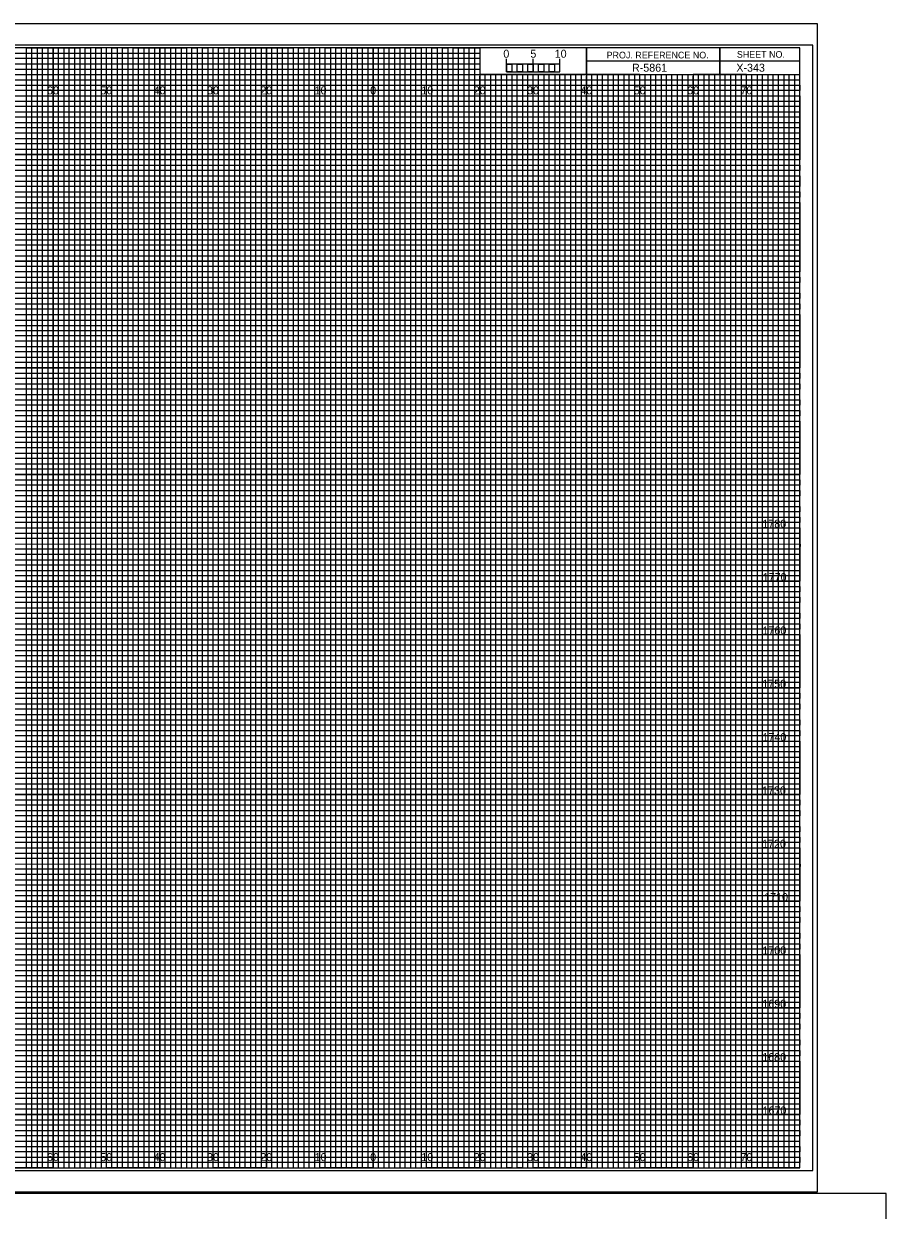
# Model space of a CAD drawing. Extents: x -13 to 1780, y -15 to 3284.
# Drawn here: x 901.7 to 1063.4, y 647.5 to 869.9 of the extents above; entities that cross this region are included whole.
import ezdxf

# ---------------------------------------------------------------- set-up
doc = ezdxf.new("R2010")
doc.units = 0
for name, color, linetype in [('Exist CMT Pavement', 7, 'Continuous'), ('Prop Retaining Wall', 7, 'Continuous'), ('Prop SS Cut Line', 7, 'Continuous'), ('Prop SS Fill Line', 7, 'Continuous'), ('Prop SS Transition Line', 7, 'Continuous'), ('Prop XS Bar Scale Labels', 7, 'Continuous'), ('Prop XS Earthwork Shape', 7, 'Continuous'), ('Prop XS Noise Wall', 7, 'Continuous'), ('Prop XS Retaining Wall', 7, 'Continuous'), ('Prop XS Station Labels', 7, 'Continuous'), ('Raster_Level_0', 7, 'Continuous'), ('Scratch_Level_3', 7, 'Continuous'), ('Scratch_Level_7', 7, 'Continuous'), ('Typical Bridge Rail CELL', 7, 'Continuous'), ('Typical Median Barrier CELL', 7, 'Continuous')]:
    doc.layers.add(name, color=color, linetype=linetype)

msp = doc.modelspace()

# ---------------------------------------------------------------- linework, layer by layer
at = {"layer": 'Prop Retaining Wall'}
for p, q in [((1032.16, 865.43), (1032.16, 860.43)), ((1032.16, 860.43), (1032.16, 865.43)), ((1007.16, 862.93), (1007.16, 860.43)), ((1047.16, 862.92), (1007.16, 862.92)), ((1007.16, 860.43), (1047.16, 860.43))]:
    msp.add_line(p, q, dxfattribs=at)
for points in [[(1047.16, 865.43), (727.16, 865.43), (727.16, 655.43), (1047.16, 655.43)], [(1007.16, 865.43), (987.16, 865.43), (987.16, 860.46), (1007.16, 860.46)], [(1047.16, 865.43), (1007.16, 865.43), (1007.16, 860.43), (1047.16, 860.43)]]:
    msp.add_lwpolyline(points, close=True, dxfattribs=at)
at = {"layer": 'Prop SS Cut Line'}
for points in [[(892.16, 655.43), (902.16, 655.43), (902.16, 865.43), (912.16, 865.43), (912.16, 655.43), (922.16, 655.43), (922.16, 865.43), (932.16, 865.43), (932.16, 655.43), (942.16, 655.43), (942.16, 865.43), (952.16, 865.43), (952.16, 655.43), (962.16, 655.43), (962.16, 865.43), (972.16, 865.43), (972.16, 655.43), (982.16, 655.43), (982.16, 865.43), (987.09, 865.43), (987.16, 865.43), (987.16, 860.43), (992.15, 860.43), (992.15, 655.43), (1002.16, 655.43), (1002.16, 860.43), (1012.16, 860.43), (1012.16, 655.43), (1022.16, 655.43), (1022.16, 860.43), (1032.16, 860.43), (1032.16, 655.43), (1042.16, 655.43), (1042.16, 860.43)], [(727.16, 860.43), (1002.16, 860.43)], [(727.16, 840.43), (1047.16, 840.43), (1047.16, 850.43), (727.16, 850.43)], [(727.16, 820.43), (1047.16, 820.43), (1047.16, 830.43), (727.16, 830.43)], [(727.16, 800.43), (1047.16, 800.43), (1047.16, 810.43), (727.16, 810.43)], [(727.16, 780.43), (1047.16, 780.43), (1047.16, 790.43), (727.16, 790.43)], [(727.16, 760.43), (1047.16, 760.43), (1047.16, 770.43), (727.16, 770.43)], [(727.16, 740.43), (1047.16, 740.43), (1047.16, 750.43), (727.16, 750.43)], [(727.16, 720.43), (1047.16, 720.43), (1047.16, 730.43), (727.16, 730.43)], [(727.16, 700.43), (1047.16, 700.43), (1047.16, 710.43), (727.16, 710.43)], [(727.16, 680.43), (1047.16, 680.43), (1047.16, 690.43), (727.16, 690.43)], [(727.16, 660.43), (1047.16, 660.43), (1047.16, 670.43), (727.16, 670.43)]]:
    msp.add_lwpolyline(points, dxfattribs=at)
at = {"layer": 'Prop SS Fill Line'}
for p, q in [((917.16, 865.43), (907.16, 865.43)), ((907.16, 865.43), (907.16, 655.43)), ((917.16, 655.43), (917.16, 865.43)), ((937.16, 865.43), (927.16, 865.43)), ((927.16, 865.43), (927.16, 655.43)), ((937.16, 655.43), (937.16, 865.43)), ((957.16, 865.43), (947.16, 865.43)), ((947.16, 865.43), (947.16, 655.43)), ((957.16, 655.43), (957.16, 865.43)), ((977.16, 865.43), (967.16, 865.43)), ((967.16, 865.43), (967.16, 655.43)), ((977.16, 655.43), (977.16, 865.43)), ((987.16, 865.43), (987.16, 655.43)), ((997.16, 655.43), (997.16, 860.43)), ((1017.16, 860.43), (1007.16, 860.43)), ((1007.16, 860.43), (1007.16, 655.43)), ((1017.16, 655.43), (1017.16, 860.43)), ((1037.16, 860.43), (1027.16, 860.43)), ((1027.16, 860.43), (1027.16, 655.43)), ((1037.16, 655.43), (1037.16, 860.43)), ((907.16, 655.43), (897.16, 655.43)), ((927.16, 655.43), (917.16, 655.43)), ((947.16, 655.43), (937.16, 655.43)), ((967.16, 655.43), (957.16, 655.43)), ((987.16, 655.43), (977.16, 655.43)), ((1007.16, 655.43), (997.16, 655.43)), ((1027.16, 655.43), (1017.16, 655.43)), ((1047.16, 655.43), (1037.16, 655.43)), ((1047.16, 655.43), (1047.16, 655.43))]:
    msp.add_line(p, q, dxfattribs=at)
for points in [[(727.16, 855.43), (1047.16, 855.43), (1047.16, 845.43), (727.16, 845.43)], [(727.16, 835.43), (1047.16, 835.43), (1047.16, 825.43), (727.16, 825.43)], [(727.16, 815.43), (1047.16, 815.43), (1047.16, 805.43), (727.16, 805.43)], [(727.16, 795.43), (1047.16, 795.43), (1047.16, 785.43), (727.16, 785.43)], [(727.16, 775.43), (1047.16, 775.43), (1047.16, 765.43), (727.16, 765.43)], [(727.16, 755.43), (1047.16, 755.43), (1047.16, 745.43), (727.16, 745.43)], [(727.16, 735.43), (1047.16, 735.43), (1047.16, 725.43), (727.16, 725.43)], [(727.16, 715.43), (1047.16, 715.43), (1047.16, 705.43), (727.16, 705.43)], [(727.16, 695.43), (1047.16, 695.43), (1047.16, 685.43), (727.16, 685.43)], [(727.16, 675.43), (1047.16, 675.43), (1047.16, 665.43), (727.16, 665.43)]]:
    msp.add_lwpolyline(points, dxfattribs=at)
at = {"layer": 'Prop SS Transition Line'}
for p, q in [((727.16, 864.43), (987.16, 864.43)), ((987.16, 863.41), (727.16, 863.41)), ((987.16, 864.43), (987.16, 863.41)), ((727.16, 862.43), (987.16, 862.43)), ((987.16, 861.32), (727.16, 861.32)), ((987.16, 862.43), (987.16, 861.32)), ((727.16, 859.43), (1047.16, 859.43))]:
    msp.add_line(p, q, dxfattribs=at)
for points in [[(727.16, 858.43), (997.16, 858.43), (1047.16, 858.43), (1047.16, 857.43), (727.16, 857.43)], [(727.16, 856.43), (1047.16, 856.43), (1047.16, 854.43), (727.16, 854.43)], [(727.16, 853.43), (1047.16, 853.43), (1047.16, 852.43), (727.16, 852.41)], [(727.16, 851.43), (1047.16, 851.43), (1047.16, 849.43), (727.16, 849.43)], [(727.16, 848.43), (1047.16, 848.43), (1047.16, 847.43), (727.16, 847.43)], [(727.16, 846.43), (1047.16, 846.43), (1047.16, 844.43), (727.16, 844.43)], [(727.16, 843.43), (1047.16, 843.43), (1047.16, 842.43), (727.16, 842.43)], [(727.16, 841.43), (1047.16, 841.43), (1047.16, 839.43), (727.16, 839.43)], [(727.16, 838.43), (1047.16, 838.43), (1047.16, 837.43), (727.16, 837.43)], [(727.16, 836.43), (1047.16, 836.43), (1047.16, 834.43), (727.16, 834.43)], [(727.16, 833.43), (1047.16, 833.43), (1047.16, 832.43), (727.16, 832.43)], [(727.16, 831.43), (1047.16, 831.43), (1047.16, 829.38), (1047.16, 828.43), (1047.16, 827.43), (727.16, 827.43)], [(727.16, 829.43), (1047.16, 829.43), (1047.16, 828.43), (727.16, 828.43)], [(727.16, 826.43), (1047.16, 826.43), (1047.16, 824.43), (727.16, 824.46)], [(727.16, 824.46), (1047.16, 824.43), (1047.16, 823.43), (727.16, 823.43)], [(727.16, 822.43), (1047.16, 822.43), (1047.16, 821.43), (727.16, 821.43)], [(727.16, 819.43), (1047.16, 819.43), (1047.16, 818.43), (727.16, 818.43)], [(727.16, 817.43), (1047.16, 817.43), (1047.16, 816.43), (727.16, 816.43)], [(727.09, 814.32), (1047.16, 814.32), (1047.16, 813.31), (727.09, 813.31)], [(727.16, 812.43), (1047.16, 812.43), (1047.16, 811.43), (727.16, 811.43)], [(727.16, 809.43), (1047.16, 809.43), (1047.16, 808.43), (727.16, 808.43)], [(727.16, 807.43), (1047.16, 807.43), (1047.16, 806.43), (727.16, 806.43)], [(727.16, 804.43), (1047.16, 804.43), (1047.16, 803.43), (727.16, 803.43)], [(727.16, 802.43), (1047.16, 802.43), (1047.16, 801.43), (727.16, 801.43)], [(727.16, 799.43), (1047.16, 799.43), (1047.16, 798.43), (727.16, 798.43)], [(727.16, 797.43), (1047.16, 797.43), (1047.16, 796.43), (727.16, 796.43)], [(727.16, 794.43), (1047.16, 794.43), (1047.15, 793.41), (727.16, 793.43)], [(727.16, 792.43), (1047.16, 792.43), (1047.16, 791.43), (727.16, 791.43)], [(727.16, 789.43), (1047.16, 789.43), (1047.16, 788.43), (727.16, 788.43)], [(727.16, 787.43), (1047.16, 787.43), (1047.16, 786.43), (727.16, 786.43)], [(727.16, 784.43), (1047.16, 784.43), (1047.16, 783.43), (727.16, 783.43)], [(727.16, 782.43), (1047.16, 782.43), (1047.16, 781.43), (727.16, 781.43)], [(727.16, 779.43), (1047.16, 779.43), (1047.16, 778.43), (727.16, 778.43)], [(727.16, 777.43), (1047.16, 777.43), (1047.16, 776.43), (727.16, 776.43)], [(727.16, 774.43), (1047.16, 774.43), (1047.16, 773.43), (727.16, 773.43)], [(727.16, 772.42), (1047.23, 772.34), (1047.16, 771.43), (727.16, 771.43)], [(727.16, 769.43), (1047.16, 769.43), (1047.16, 768.43), (727.16, 768.43)], [(727.16, 767.43), (1047.16, 767.43), (1047.16, 766.43), (727.16, 766.43)], [(727.16, 764.43), (1047.16, 764.43), (1047.16, 763.43), (727.16, 763.43)], [(727.16, 762.43), (1047.16, 762.43), (1047.16, 761.43), (727.16, 761.43)], [(727.16, 759.43), (1047.16, 759.43), (1047.16, 758.43), (727.16, 758.43)], [(727.16, 757.43), (1047.16, 757.43), (1047.16, 756.43), (727.16, 756.43)], [(727.16, 754.43), (1047.16, 754.43), (1047.16, 753.43), (727.16, 753.43)], [(727.16, 752.43), (1047.16, 752.43), (1047.16, 751.43), (727.16, 751.43)], [(727.16, 749.43), (1047.16, 749.43), (1047.16, 748.43), (727.16, 748.43)], [(727.16, 747.43), (1047.16, 747.43), (1047.16, 746.43), (727.16, 746.43)], [(727.16, 744.43), (1047.16, 744.43), (1047.16, 743.43), (727.16, 743.43)], [(727.16, 742.43), (1047.16, 742.43), (1047.16, 741.43), (727.16, 741.43)], [(727.16, 739.43), (1047.16, 739.43), (1047.16, 738.43), (727.16, 738.43)], [(727.16, 737.43), (1047.16, 737.43), (1047.16, 736.43), (727.16, 736.43)], [(727.16, 734.43), (1047.16, 734.43), (1047.15, 733.41), (727.16, 733.43)], [(727.16, 732.43), (1047.16, 732.43), (1047.16, 731.43), (727.16, 731.43)], [(727.16, 729.43), (1047.16, 729.43), (1047.16, 728.43), (727.16, 728.43)], [(727.16, 727.43), (1047.16, 727.43), (1047.16, 726.43), (727.16, 726.43)], [(727.16, 724.43), (1047.16, 724.43), (1047.16, 723.43), (727.16, 723.43)], [(727.16, 722.43), (1047.16, 722.43), (1047.16, 721.43), (727.16, 721.43)], [(727.16, 719.43), (1047.16, 719.43), (1047.16, 718.43), (727.16, 718.43)], [(727.16, 717.43), (1047.16, 717.43), (1047.16, 716.43), (727.16, 716.43)], [(727.16, 714.43), (1047.16, 714.43), (1047.16, 713.43), (727.16, 713.43)], [(727.16, 712.42), (1047.23, 712.34), (1047.16, 711.43), (727.16, 711.43)], [(727.16, 709.43), (1047.16, 709.43), (1047.16, 708.43), (727.16, 708.43)], [(727.16, 707.43), (1047.16, 707.43), (1047.16, 706.43), (727.16, 706.43)], [(727.16, 704.43), (1047.16, 704.43), (1047.16, 703.43), (727.16, 703.43)], [(727.16, 702.43), (1047.16, 702.43), (1047.16, 701.43), (727.16, 701.43)], [(727.16, 699.43), (1047.16, 699.43), (1047.16, 698.43), (727.16, 698.43)], [(727.16, 697.43), (1047.16, 697.43), (1047.16, 696.43), (727.16, 696.43)], [(727.16, 694.43), (1047.16, 694.43), (1047.16, 693.43), (727.16, 693.43)], [(727.16, 692.43), (1047.16, 692.43), (1047.16, 691.43), (727.16, 691.43)], [(727.16, 689.43), (1047.16, 689.43), (1047.16, 688.43), (727.16, 688.43)], [(727.16, 687.43), (1047.16, 687.43), (1047.16, 686.43), (727.16, 686.43)], [(727.16, 684.43), (1047.16, 684.43), (1047.16, 683.43), (727.16, 683.43)], [(727.16, 682.43), (1047.16, 682.43), (1047.16, 681.43), (727.16, 681.43)], [(727.16, 679.43), (1047.16, 679.43), (1047.16, 678.43), (727.16, 678.43)], [(727.16, 677.43), (1047.16, 677.43), (1047.16, 676.43), (727.16, 676.43)], [(727.16, 674.43), (1047.16, 674.43), (1047.16, 673.43), (727.16, 673.43)], [(727.16, 672.43), (1047.16, 672.43), (1047.16, 671.43), (727.16, 671.43)], [(727.16, 669.43), (1047.16, 669.43), (1047.16, 668.43), (727.16, 668.43)], [(727.16, 667.43), (1047.16, 667.43), (1047.16, 666.43), (727.16, 666.43)], [(727.16, 664.43), (1047.16, 664.43), (1047.16, 663.43), (727.16, 663.43)], [(727.16, 662.43), (1047.16, 662.43), (1047.16, 661.43), (727.16, 661.43)], [(727.16, 659.43), (1047.16, 659.43), (1047.16, 658.43), (727.16, 658.43)], [(727.16, 657.43), (1047.16, 657.43), (1047.16, 656.43), (727.16, 656.43)]]:
    msp.add_lwpolyline(points, dxfattribs=at)
at = {"layer": 'Prop XS Earthwork Shape'}
for points in [[(713.76, 650.93), (1050.46, 650.93), (1050.46, 869.93), (713.76, 869.93)], [(726.66, 431.62), (1063.36, 431.62), (1063.36, 650.62), (726.66, 650.62)]]:
    msp.add_lwpolyline(points, close=True, dxfattribs=at)
at = {"layer": 'Prop XS Noise Wall'}
for p, q in [((907.16, 655.43), (907.16, 865.43)), ((917.16, 655.43), (917.16, 865.43)), ((927.16, 655.43), (927.16, 865.43)), ((937.16, 655.43), (937.16, 865.43)), ((947.16, 655.43), (947.16, 865.43)), ((957.16, 655.43), (957.16, 865.43)), ((967.16, 655.43), (967.16, 865.43)), ((977.16, 655.43), (977.16, 865.43)), ((987.16, 655.43), (987.16, 860.11)), ((997.16, 655.43), (997.16, 860.11)), ((1007.16, 655.43), (1007.16, 860.11)), ((1017.16, 655.43), (1017.16, 860.11)), ((1027.16, 655.43), (1027.16, 860.11)), ((1037.16, 655.43), (1037.16, 860.11)), ((727.16, 855.43), (1047.16, 855.43)), ((727.16, 845.43), (1047.16, 845.43)), ((727.16, 835.43), (1047.16, 835.43)), ((727.16, 825.43), (1047.16, 825.43)), ((727.16, 815.43), (1047.16, 815.43)), ((727.16, 805.43), (1047.16, 805.43)), ((727.16, 795.43), (1047.16, 795.43)), ((727.16, 785.43), (1047.16, 785.43)), ((727.16, 775.43), (1047.16, 775.43)), ((727.16, 765.43), (1047.16, 765.43)), ((727.16, 755.43), (1047.16, 755.43)), ((727.16, 745.43), (1047.16, 745.43)), ((727.16, 735.43), (1047.16, 735.43)), ((727.16, 725.43), (1047.16, 725.43)), ((727.16, 715.43), (1047.16, 715.43)), ((727.16, 705.43), (1047.16, 705.43)), ((727.16, 695.43), (1047.16, 695.43)), ((727.16, 685.43), (1047.16, 685.43)), ((727.16, 675.43), (1047.16, 675.43)), ((727.16, 665.43), (1047.16, 665.43))]:
    msp.add_line(p, q, dxfattribs=at)
at = {"layer": 'Prop XS Retaining Wall'}
for p, q in [((992.16, 860.92), (992.16, 863.33)), ((992.16, 862.33), (992.16, 863.33)), ((997.16, 860.92), (997.16, 863.33)), ((1002.16, 860.92), (1002.16, 863.33)), ((1002.16, 862.33), (1002.16, 863.33))]:
    msp.add_line(p, q, dxfattribs=at)
for points in [[(1002.16, 862.33), (992.16, 862.33), (992.16, 860.92), (1002.16, 860.92)], [(992.16, 862.33), (993.16, 862.33), (993.16, 860.92), (992.16, 860.92)], [(994.16, 862.33), (995.16, 862.33), (995.16, 860.92), (994.16, 860.92)], [(996.16, 862.33), (997.16, 862.33), (997.16, 860.92), (996.16, 860.92)], [(998.16, 862.33), (999.16, 862.33), (999.16, 860.92), (998.16, 860.92)], [(1000.16, 862.33), (1001.16, 862.33), (1001.16, 860.92), (1000.16, 860.92)]]:
    msp.add_lwpolyline(points, close=True, dxfattribs=at)
at = {"layer": 'Prop XS Station Labels'}
for p, q in [((1050.46, 869.93), (713.76, 869.93)), ((713.76, 650.93), (1050.46, 650.93)), ((1063.36, 650.62), (726.66, 650.62))]:
    msp.add_line(p, q, dxfattribs=at)
at = {"layer": 'Scratch_Level_7'}
msp.add_lwpolyline([(716.36, 654.93), (1049.56, 654.93), (1049.56, 865.93), (716.36, 865.93)], close=True, dxfattribs=at)
at = {"layer": 'Typical Bridge Rail CELL'}
for p, q in [((994.16, 860.43), (993.17, 860.43)), ((993.17, 860.43), (993.17, 655.43)), ((994.16, 655.43), (994.16, 860.43)), ((996.16, 860.43), (995.16, 860.43)), ((995.16, 860.43), (995.16, 655.43)), ((996.16, 655.43), (996.16, 860.43)), ((993.17, 655.43), (992.16, 655.43)), ((995.16, 655.43), (994.16, 655.43))]:
    msp.add_line(p, q, dxfattribs=at)
for points in [[(902.16, 655.43), (903.16, 655.43), (903.16, 865.43), (904.16, 865.43), (904.16, 655.43)], [(904.16, 655.43), (905.16, 655.43), (905.16, 865.43), (906.16, 865.43), (906.16, 655.43)], [(907.16, 655.43), (908.16, 655.43), (908.16, 865.43), (909.16, 865.43), (909.16, 655.43)], [(909.16, 655.43), (910.16, 655.43), (910.16, 865.43), (911.16, 865.43), (911.16, 655.43)], [(912.16, 655.43), (913.16, 655.43), (913.16, 865.43), (914.16, 865.43), (914.16, 655.43)], [(914.16, 655.43), (915.16, 655.43), (915.16, 865.43), (916.16, 865.43), (916.16, 655.43)], [(917.16, 655.43), (918.16, 655.43), (918.16, 865.43), (919.16, 865.43), (919.16, 655.43)], [(919.16, 655.43), (920.16, 655.43), (920.16, 865.43), (921.16, 865.43), (921.16, 655.43)], [(922.16, 655.43), (923.16, 655.43), (923.16, 865.43), (924.16, 865.43), (924.16, 655.43)], [(924.16, 655.43), (925.16, 655.43), (925.16, 865.43), (926.16, 865.43), (926.16, 655.43)], [(927.16, 655.43), (928.16, 655.43), (928.16, 865.43), (929.16, 865.43), (929.16, 655.43)], [(929.16, 655.43), (930.16, 655.43), (930.16, 865.43), (931.16, 865.43), (931.16, 655.43)], [(932.16, 655.43), (933.16, 655.43), (933.16, 865.43), (934.16, 865.43), (934.16, 655.43)], [(934.16, 655.43), (935.16, 655.43), (935.16, 865.43), (936.16, 865.43), (936.16, 655.43)], [(937.16, 655.43), (938.16, 655.43), (938.16, 865.43), (939.16, 865.43), (939.16, 655.43)], [(939.16, 655.43), (940.16, 655.43), (940.16, 865.43), (941.16, 865.43), (941.16, 655.43)], [(942.16, 655.43), (943.16, 655.43), (943.16, 865.43), (944.16, 865.43), (944.16, 655.43)], [(944.16, 655.43), (945.16, 655.43), (945.16, 865.43), (946.16, 865.43), (946.16, 655.43)], [(947.16, 655.43), (948.16, 655.43), (948.16, 865.43), (949.16, 865.43), (949.16, 655.43)], [(949.16, 655.43), (950.16, 655.43), (950.16, 865.43), (951.16, 865.43), (951.16, 655.43)], [(952.16, 655.43), (953.16, 655.43), (953.16, 865.43), (954.16, 865.43), (954.16, 655.43)], [(954.16, 655.43), (955.16, 655.43), (955.16, 865.43), (956.16, 865.43), (956.16, 655.43)], [(957.16, 655.43), (958.16, 655.43), (958.16, 865.43), (959.16, 865.43), (959.16, 655.43)], [(959.16, 655.43), (960.16, 655.43), (960.16, 865.43), (961.16, 865.43), (961.16, 655.43)], [(962.16, 655.43), (963.16, 655.43), (963.16, 865.43), (964.16, 865.43), (964.16, 655.43)], [(964.16, 655.43), (965.16, 655.43), (965.16, 865.43), (966.16, 865.43), (966.16, 655.43)], [(967.16, 655.43), (968.16, 655.43), (968.16, 865.43), (969.16, 865.43), (969.16, 655.43)], [(969.16, 655.43), (970.16, 655.43), (970.16, 865.43), (971.16, 865.43), (971.16, 655.43)], [(972.16, 655.43), (973.16, 655.43), (973.16, 865.43), (974.16, 865.43), (974.16, 655.43)], [(974.16, 655.43), (975.16, 655.43), (975.16, 865.43), (976.16, 865.43), (976.16, 655.43)], [(977.16, 655.43), (978.16, 655.43), (978.16, 865.43), (979.16, 865.43), (979.16, 655.43)], [(979.16, 655.43), (980.16, 655.43), (980.16, 865.43), (981.16, 865.43), (981.16, 655.43)], [(982.16, 655.43), (983.16, 655.43), (983.16, 865.43), (984.16, 865.43), (984.16, 655.43)], [(984.16, 655.43), (985.16, 655.43), (985.16, 865.43), (986.16, 865.43), (986.16, 655.43)], [(987.16, 655.43), (988.16, 655.43), (988.16, 860.43), (989.18, 860.43), (989.18, 655.43)], [(989.16, 655.43), (990.16, 655.43), (990.16, 860.43), (991.15, 860.43), (991.15, 655.43)], [(997.16, 655.43), (998.14, 655.43), (998.14, 860.43), (999.16, 860.43), (999.16, 655.43)], [(999.16, 655.43), (1000.16, 655.43), (1000.16, 860.43), (1001.21, 860.43), (1001.21, 655.43)], [(1002.16, 655.43), (1003.16, 655.43), (1003.16, 860.43), (1004.16, 860.43), (1004.16, 655.43)], [(1004.16, 655.43), (1005.16, 655.43), (1005.16, 860.43), (1006.16, 860.43), (1006.16, 655.43)], [(1007.16, 655.43), (1008.16, 655.43), (1008.16, 860.43), (1009.16, 860.43), (1009.16, 655.43)], [(1009.16, 655.43), (1010.16, 655.43), (1010.16, 860.43), (1011.16, 860.43), (1011.16, 655.43)], [(1012.16, 655.43), (1013.16, 655.43), (1013.16, 860.43), (1014.16, 860.43), (1014.16, 655.43)], [(1014.16, 655.43), (1015.16, 655.43), (1015.16, 860.43), (1016.16, 860.43), (1016.16, 655.43)], [(1017.16, 655.43), (1018.16, 655.43), (1018.16, 860.43), (1019.16, 860.43), (1019.16, 655.43)], [(1019.16, 655.43), (1020.16, 655.43), (1020.16, 860.43), (1021.16, 860.43), (1021.16, 655.43)], [(1022.16, 655.43), (1023.16, 655.43), (1023.16, 860.43), (1024.16, 860.43), (1024.16, 655.43)], [(1024.16, 655.43), (1025.16, 655.43), (1025.16, 860.43), (1026.16, 860.43), (1026.16, 655.43)], [(1027.16, 655.43), (1028.16, 655.43), (1028.16, 860.43), (1029.16, 860.43), (1029.16, 655.43)], [(1029.16, 655.43), (1030.16, 655.43), (1030.16, 860.43), (1031.16, 860.43), (1031.16, 655.43)], [(1032.16, 655.43), (1033.16, 655.43), (1033.16, 860.43), (1034.16, 860.43), (1034.16, 655.43)], [(1034.16, 655.43), (1035.16, 655.43), (1035.16, 860.43), (1036.16, 860.43), (1036.16, 655.43)], [(1037.16, 655.43), (1038.16, 655.43), (1038.16, 860.43), (1039.16, 860.43), (1039.16, 655.43)], [(1039.16, 655.43), (1040.16, 655.43), (1040.16, 860.43), (1041.16, 860.43), (1041.16, 655.43)], [(1042.16, 655.43), (1043.16, 655.43), (1043.16, 860.43), (1044.16, 860.43), (1044.16, 655.43)], [(1044.16, 655.43), (1045.16, 655.43), (1045.16, 860.43), (1046.16, 860.43), (1046.16, 655.43)]]:
    msp.add_lwpolyline(points, dxfattribs=at)

# ---------------------------------------------------------------- texts
at = {"layer": 'Exist CMT Pavement'}
msp.add_text('R-5861', height=1.5, dxfattribs=at).set_placement((1015.69, 860.93))
at = {"layer": 'Prop Retaining Wall'}
for s, p in [('PROJ. REFERENCE NO.', (1010.93, 863.42)), ('SHEET NO.', (1035.35, 863.55))]:
    msp.add_text(s, height=1.25, dxfattribs=at).set_placement(p)
at = {"layer": 'Prop XS Bar Scale Labels'}
for s, p in [('5', (996.64, 863.55)), ('10', (1001.2, 863.55))]:
    msp.add_text(s, height=1.5, dxfattribs=at).set_placement(p)
at = {"layer": 'Prop XS Retaining Wall'}
msp.add_text('0', height=1.5, dxfattribs=at).set_placement((991.57, 863.55))
at = {"layer": 'Raster_Level_0'}
for s, p in [('60', (906.02, 856.68)), ('50', (916.02, 856.68)), ('40', (926.02, 856.68)), ('30', (936.02, 856.68)), ('20', (946.02, 856.68)), ('10', (956.2, 856.68)), ('0', (966.61, 856.68)), ('0', (966.61, 856.68)), ('10', (976.2, 856.68)), ('20', (986.02, 856.68)), ('30', (996.02, 856.68)), ('40', (1006.02, 856.68)), ('50', (1016.02, 856.68)), ('60', (1026.02, 856.68)), ('70', (1036.02, 856.68)), ('60', (906.02, 656.68)), ('50', (916.02, 656.68)), ('40', (926.02, 656.68)), ('30', (936.02, 656.68)), ('20', (946.02, 656.68)), ('10', (956.2, 656.68)), ('0', (966.61, 656.68)), ('0', (966.61, 656.68)), ('10', (976.2, 656.68)), ('20', (986.02, 656.68)), ('30', (996.02, 656.68)), ('40', (1006.02, 656.68)), ('50', (1016.02, 656.68)), ('60', (1026.02, 656.68)), ('70', (1036.02, 656.68))]:
    msp.add_text(s, height=1.5, dxfattribs=at).set_placement(p)
at = {"layer": 'Scratch_Level_3'}
for s, p in [('1780', (1040.14, 775.43)), ('1770', (1040.2, 765.43)), ('1760', (1040.16, 755.43)), ('1750', (1040.12, 745.43)), ('1740', (1040.16, 735.43)), ('1730', (1040.08, 725.43)), ('1720', (1040.09, 715.43)), ('1710', (1040.47, 705.43)), ('1700', (1040.14, 695.43)), ('1690', (1040.13, 685.43)), ('1680', (1040.11, 675.43)), ('1670', (1040.16, 665.43))]:
    msp.add_text(s, height=1.5, dxfattribs=at).set_placement(p)
at = {"layer": 'Typical Median Barrier CELL'}
msp.add_text('X-343', height=1.5, dxfattribs=at).set_placement((1035.25, 860.93))

doc.saveas('drawing.dxf')
